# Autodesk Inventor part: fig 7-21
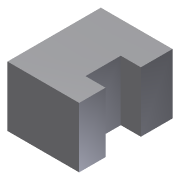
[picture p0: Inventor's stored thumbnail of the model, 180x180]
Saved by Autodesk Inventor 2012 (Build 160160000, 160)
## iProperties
Created: 2010-03
Part Number: fig 7-21
Document SubType Name: Modeling
Designer: CADSoft
Density: 1 g/cm^3
Material: Default
Author: CADSoft
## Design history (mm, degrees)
sketch "Sketch1"
  geometry: L1 (-16.027, 20.205)-(19.726, 20.205); L2 (19.726, 20.205)-(19.726, -26.37); L3 (19.726, -26.37)-(-16.027, -26.37); L4 (-16.027, -26.37)-(-16.027, 20.205); 1 further point
  constraints: 8 end point, 2 parallel, 1 horizontal, 1 perpendicular
extrude "Extrusion1" new body sketch "Sketch1" distance "d0" = 30; taper "d1" = 0 deg
sketch "Sketch2"
  geometry: L1 (-30, 46.575)-(-30, 0) reference; L2 (0, 46.575)-(0, 0) reference; L3 (-30, 13.159)-(0, 13.159); L4 (0, 13.159)-(0, 33.527); L5 (0, 33.527)-(-30, 33.527); L6 (-30, 33.527)-(-30, 13.159); 1 further point
  constraints: 8 end point, 2 parallel, 2 point on line, 1 horizontal, 1 perpendicular
extrude "Extrusion2" cut sketch "Sketch2" distance "d2" = 10; taper "d3" = 0 deg
feature "Move Face1"
body "Solid1"
